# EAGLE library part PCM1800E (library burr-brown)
Single-Ended Analog Input 20-Bit Stereo ADC
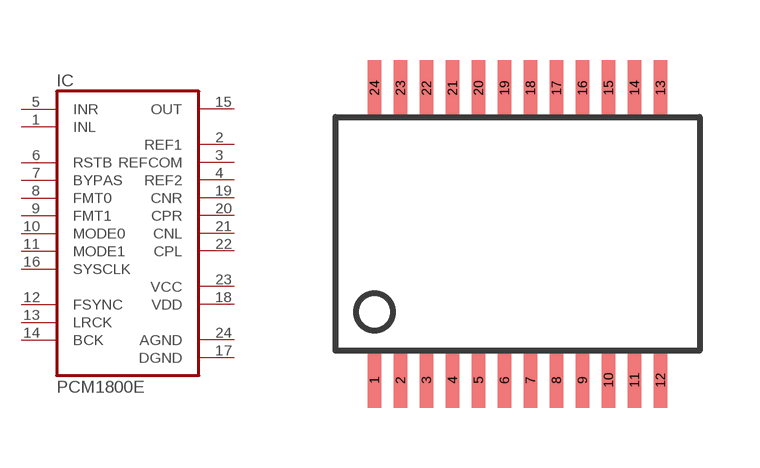
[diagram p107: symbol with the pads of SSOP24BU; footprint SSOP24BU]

Designator prefix IC

## PCM1800E (MF: TEXAS INSTRUMENTS; MPN: PCM1800E; OC_FARNELL: 1648631; OC_NEWARK: 34K8598)  [SSOP24BU]
1  INL  in
2  REF1  pas
3  REFCOM  pas
4  REF2  pas
5  INR  in
6  RSTB  in
7  BYPAS  in
8  FMT0  in
9  FMT1  in
10  MODE0  in
11  MODE1  in
12  FSYNC
13  LRCK
14  BCK
15  OUT  out
16  SYSCLK  in
17  DGND  pwr
18  VDD  pwr
19  CNR  pas
20  CPR  pas
21  CNL  pas
22  CPL  pas
23  VCC  pwr
24  AGND  pwr

## Footprint SSOP24BU (pad centres in mm)
Small Shrink Outline Package
smd 0.348 x 1.397: 1 -3.575,-3.656; 2 -2.925,-3.656; 3 -2.275,-3.656; 4 -1.625,-3.656; 5 -0.975,-3.656; 6 -0.325,-3.656; 7 0.325,-3.656; 8 0.975,-3.656; 9 1.625,-3.656; 10 2.275,-3.656; 11 2.925,-3.656; 12 3.575,-3.656; 13 3.575,3.656; 14 2.925,3.656; 15 2.275,3.656; 16 1.625,3.656; 17 0.975,3.656; 18 0.325,3.656; 19 -0.325,3.656; 20 -0.975,3.656; 21 -1.625,3.656; 22 -2.275,3.656; 23 -2.925,3.656; 24 -3.575,3.656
